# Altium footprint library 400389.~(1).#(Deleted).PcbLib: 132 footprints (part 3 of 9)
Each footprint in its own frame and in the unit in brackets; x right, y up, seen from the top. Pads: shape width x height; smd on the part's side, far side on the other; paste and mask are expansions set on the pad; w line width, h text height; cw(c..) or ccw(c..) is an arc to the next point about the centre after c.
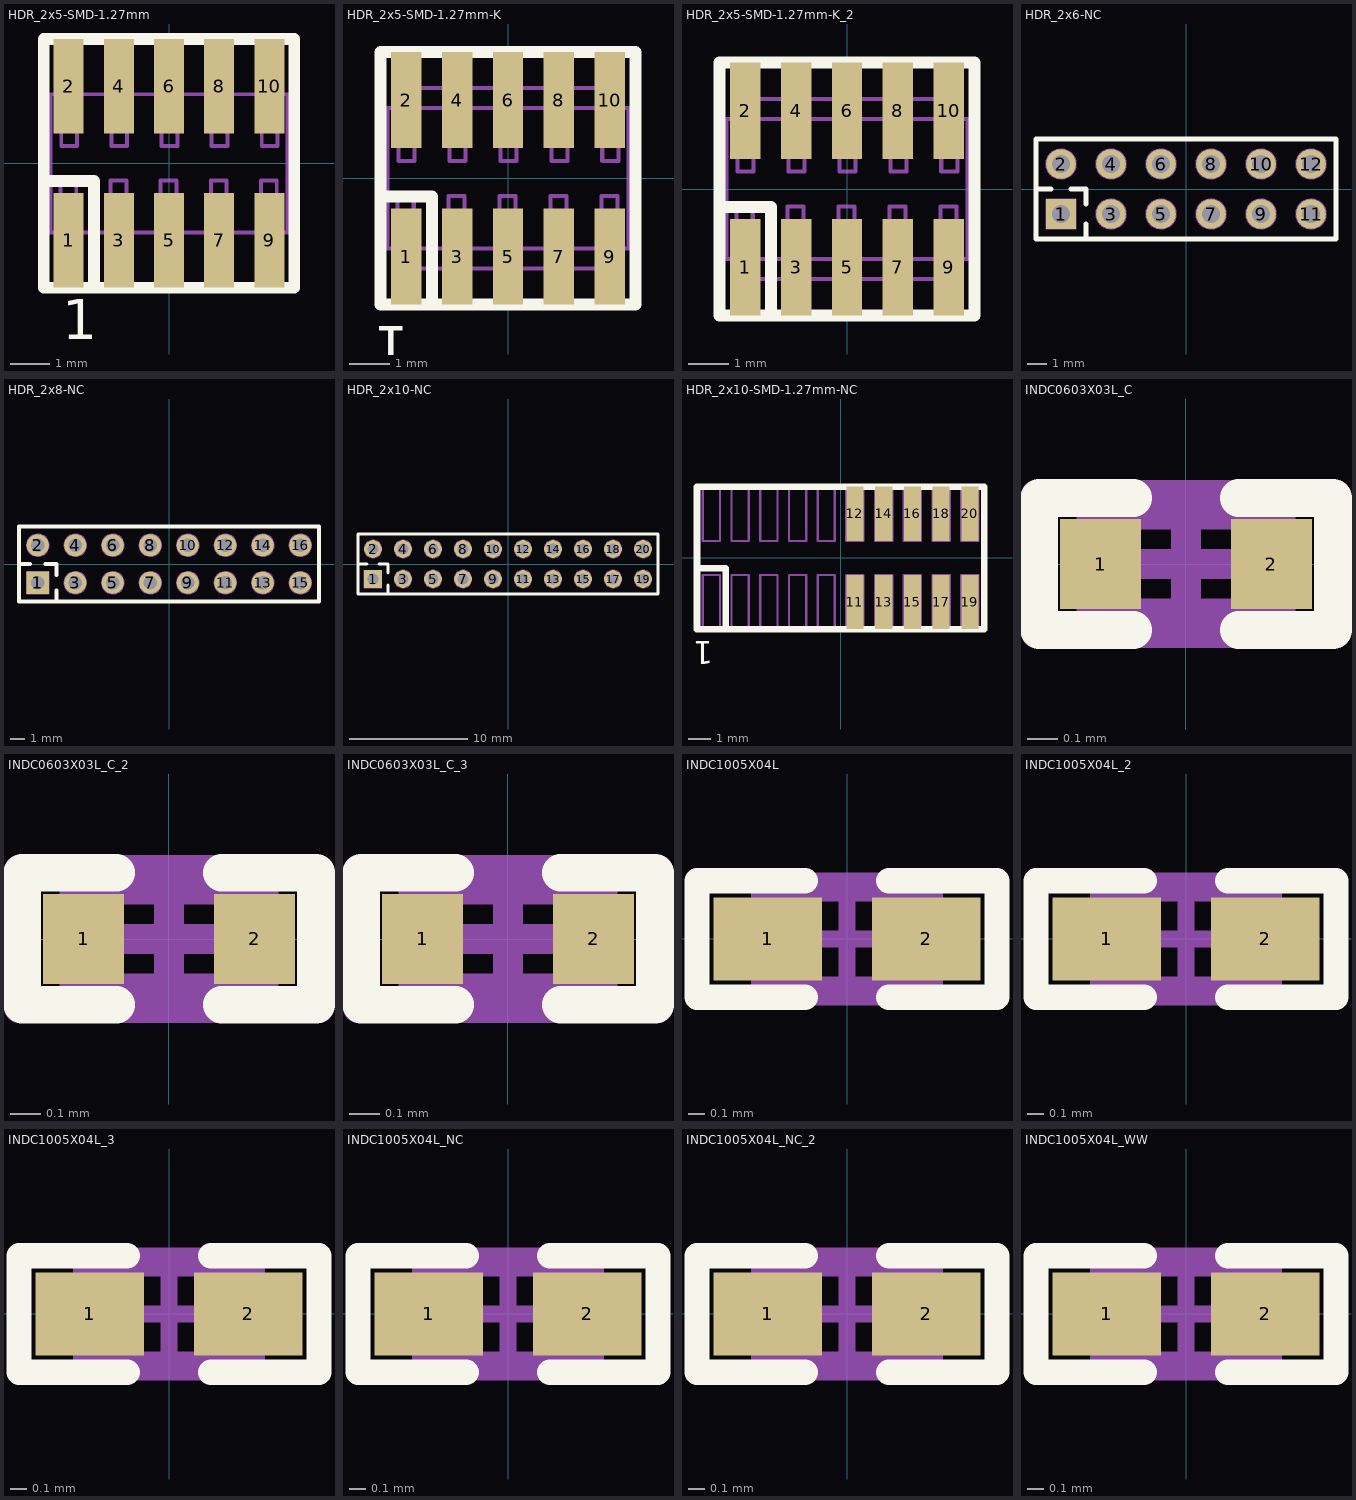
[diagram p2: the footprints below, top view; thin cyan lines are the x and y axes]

## HDR_2x5-SMD-1.27mm [mm]
pads (10):
  rect 0.76x2.4 smd: 1(-2.54,-1.95) 2(-2.54,1.95) 3(-1.27,-1.95) 4(-1.27,1.95) 5(0,-1.95) 6(0,1.95) 7(1.27,-1.95) 8(1.27,1.95) 9(2.54,-1.95) 10(2.54,1.95)
Top Overlay:
  lines w0.3: -3.175,-0.45 -1.9,-0.45 -1.9,-3.15 ; -3.175,-3.15 -3.175,3.15 3.175,3.15 3.175,-3.15 -3.175,-3.15
  text "1" at -2.7,-4.45 h1.02
Mechanical 7:
  lines w0.1: -2.74,-1.75 -2.74,-2.459 ccw(c-2.54,-2.459) -2.34,-2.459 -2.34,-1.75 ; -2.74,1.75 -2.74,2.459 cw(c-2.54,2.459) -2.34,2.459 -2.34,1.75 ; -1.47,-1.75 -1.47,-2.459 ccw(c-1.27,-2.459) -1.07,-2.459 -1.07,-1.75 ; -1.47,1.75 -1.47,2.459 cw(c-1.27,2.459) -1.07,2.459 -1.07,1.75 ; -0.2,-1.75 -0.2,-2.459 ccw(c0,-2.459) 0.2,-2.459 0.2,-1.75 ; -0.2,1.75 -0.2,2.459 cw(c0,2.459) 0.2,2.459 0.2,1.75 ; 1.07,-1.75 1.07,-2.459 ccw(c1.27,-2.459) 1.47,-2.459 1.47,-1.75 ; 1.07,1.75 1.07,2.459 cw(c1.27,2.459) 1.47,2.459 1.47,1.75 ; 2.34,-1.75 2.34,-2.459 ccw(c2.54,-2.459) 2.74,-2.459 2.74,-1.75 ; 2.34,1.75 2.34,2.459 cw(c2.54,2.459) 2.74,2.459 2.74,1.75 ; -3,-1.75 3,-1.75 3,1.75 -3,1.75 -3,-1.75 ; -2.75,-0.835 -2.35,-0.835 -2.35,-0.435 -2.75,-0.435 -2.75,-0.835 ; -2.73,0.435 -2.33,0.435 -2.33,0.835 -2.73,0.835 -2.73,0.435 ; -1.48,-0.835 -1.08,-0.835 -1.08,-0.435 -1.48,-0.435 -1.48,-0.835 ; -1.46,0.435 -1.06,0.435 -1.06,0.835 -1.46,0.835 -1.46,0.435 ; -0.21,-0.835 0.19,-0.835 0.19,-0.435 -0.21,-0.435 -0.21,-0.835 ; -0.19,0.435 0.21,0.435 0.21,0.835 -0.19,0.835 -0.19,0.435 ; 1.06,-0.835 1.46,-0.835 1.46,-0.435 1.06,-0.435 1.06,-0.835 ; 1.08,0.435 1.48,0.435 1.48,0.835 1.08,0.835 1.08,0.435 ; 2.33,-0.835 2.73,-0.835 2.73,-0.435 2.33,-0.435 2.33,-0.835 ; 2.35,0.435 2.75,0.435 2.75,0.835 2.35,0.835 2.35,0.435
  text ".Designator" at -0.8,-0.2 h0.38
3D body "Samtec-FTS-105-01-F-DV.step": height 4.33, standoff 0.01, extent -3.165,-2.921 3.185,2.921

## HDR_2x5-SMD-1.27mm-K [mm]
pads (10):
  rect 0.76x2.4 smd: 1(-2.54,-1.95) 2(-2.54,1.95) 3(-1.27,-1.95) 4(-1.27,1.95) 5(0,-1.95) 6(0,1.95) 7(1.27,-1.95) 8(1.27,1.95) 9(2.54,-1.95) 10(2.54,1.95)
Top Overlay:
  lines w0.3: -3.175,-0.45 -1.9,-0.45 -1.9,-3.15 ; -3.175,-3.15 -3.175,3.15 3.175,3.15 3.175,-3.15 -3.175,-3.15
  text "1" at -2.448,-3.683 h1.02
Mechanical 7:
  lines w0.1: -2.74,-1.75 -2.74,-2.459 ccw(c-2.54,-2.459) -2.34,-2.459 -2.34,-2.25 ; -2.74,1.75 -2.74,2.459 cw(c-2.54,2.459) -2.34,2.459 -2.34,2.25 ; -2.5,-1.75 -2.5,-2.25 -1.25,-2.25 ; -2.5,1.75 -2.5,2.25 2.5,2.25 2.5,1.75 ; -1.47,-2.25 -1.47,-2.459 ccw(c-1.27,-2.459) -1.07,-2.459 -1.07,-2.25 ; -1.47,2.25 -1.47,2.459 cw(c-1.27,2.459) -1.07,2.459 -1.07,2.25 ; -1.25,-1.75 -1.25,-2.25 ; -0.2,-2.25 -0.2,-2.459 ccw(c0,-2.459) 0.2,-2.459 0.2,-2.25 ; -0.2,2.25 -0.2,2.459 cw(c0,2.459) 0.2,2.459 0.2,2.25 ; 1.07,-2.25 1.07,-2.459 ccw(c1.27,-2.459) 1.47,-2.459 1.47,-2.25 ; 1.07,2.25 1.07,2.459 cw(c1.27,2.459) 1.47,2.459 1.47,2.25 ; 1.25,-1.75 1.25,-2.25 ; 2.34,-2.25 2.34,-2.459 ccw(c2.54,-2.459) 2.74,-2.459 2.74,-1.75 ; 2.34,2.25 2.34,2.459 cw(c2.54,2.459) 2.74,2.459 2.74,1.75 ; 2.5,-1.75 2.5,-2.25 1.25,-2.25 ; -1.25,-2.25 1.25,-2.25 ; -3,-1.75 -3,1.75 3,1.75 3,-1.75 -3,-1.75 ; -2.75,-0.835 -2.75,-0.435 -2.35,-0.435 -2.35,-0.835 -2.75,-0.835 ; -2.73,0.435 -2.73,0.835 -2.33,0.835 -2.33,0.435 -2.73,0.435 ; -1.48,-0.835 -1.48,-0.435 -1.08,-0.435 -1.08,-0.835 -1.48,-0.835 ; -1.46,0.435 -1.46,0.835 -1.06,0.835 -1.06,0.435 -1.46,0.435 ; -0.21,-0.835 -0.21,-0.435 0.19,-0.435 0.19,-0.835 -0.21,-0.835 ; -0.19,0.435 -0.19,0.835 0.21,0.835 0.21,0.435 -0.19,0.435 ; 1.06,-0.835 1.06,-0.435 1.46,-0.435 1.46,-0.835 1.06,-0.835 ; 1.08,0.435 1.08,0.835 1.48,0.835 1.48,0.435 1.08,0.435 ; 2.33,-0.835 2.33,-0.435 2.73,-0.435 2.73,-0.835 2.33,-0.835 ; 2.35,0.435 2.35,0.835 2.75,0.835 2.75,0.435 2.35,0.435
  text ".Designator" at -0.8,-0.2 h0.38
3D body "Samtec-FTSH-105-01-F-DV-K.step": height 6.11, standoff -0.01, extent -3.137,-2.921 3.137,2.921

## HDR_2x5-SMD-1.27mm-K_2 [mm]
pads (10):
  rect 0.76x2.4 smd: 1(-2.54,-1.95) 2(-2.54,1.95) 3(-1.27,-1.95) 4(-1.27,1.95) 5(0,-1.95) 6(0,1.95) 7(1.27,-1.95) 8(1.27,1.95) 9(2.54,-1.95) 10(2.54,1.95)
Top Overlay:
  lines w0.3: -3.175,-0.45 -1.9,-0.45 -1.9,-3.15 ; -3.175,-3.15 -3.175,3.15 3.175,3.15 3.175,-3.15 -3.175,-3.15
Mechanical 7:
  lines w0.1: -2.74,-1.75 -2.74,-2.459 ccw(c-2.54,-2.459) -2.34,-2.459 -2.34,-2.25 ; -2.74,1.75 -2.74,2.459 cw(c-2.54,2.459) -2.34,2.459 -2.34,2.25 ; -2.5,-1.75 -2.5,-2.25 -1.25,-2.25 ; -2.5,1.75 -2.5,2.25 2.5,2.25 2.5,1.75 ; -1.47,-2.25 -1.47,-2.459 ccw(c-1.27,-2.459) -1.07,-2.459 -1.07,-2.25 ; -1.47,2.25 -1.47,2.459 cw(c-1.27,2.459) -1.07,2.459 -1.07,2.25 ; -1.25,-1.75 -1.25,-2.25 ; -0.2,-2.25 -0.2,-2.459 ccw(c0,-2.459) 0.2,-2.459 0.2,-2.25 ; -0.2,2.25 -0.2,2.459 cw(c0,2.459) 0.2,2.459 0.2,2.25 ; 1.07,-2.25 1.07,-2.459 ccw(c1.27,-2.459) 1.47,-2.459 1.47,-2.25 ; 1.07,2.25 1.07,2.459 cw(c1.27,2.459) 1.47,2.459 1.47,2.25 ; 1.25,-1.75 1.25,-2.25 ; 2.34,-2.25 2.34,-2.459 ccw(c2.54,-2.459) 2.74,-2.459 2.74,-1.75 ; 2.34,2.25 2.34,2.459 cw(c2.54,2.459) 2.74,2.459 2.74,1.75 ; 2.5,-1.75 2.5,-2.25 1.25,-2.25 ; -1.25,-2.25 1.25,-2.25 ; -3,-1.75 -3,1.75 3,1.75 3,-1.75 -3,-1.75 ; -2.75,-0.835 -2.75,-0.435 -2.35,-0.435 -2.35,-0.835 -2.75,-0.835 ; -2.73,0.435 -2.73,0.835 -2.33,0.835 -2.33,0.435 -2.73,0.435 ; -1.48,-0.835 -1.48,-0.435 -1.08,-0.435 -1.08,-0.835 -1.48,-0.835 ; -1.46,0.435 -1.46,0.835 -1.06,0.835 -1.06,0.435 -1.46,0.435 ; -0.21,-0.835 -0.21,-0.435 0.19,-0.435 0.19,-0.835 -0.21,-0.835 ; -0.19,0.435 -0.19,0.835 0.21,0.835 0.21,0.435 -0.19,0.435 ; 1.06,-0.835 1.06,-0.435 1.46,-0.435 1.46,-0.835 1.06,-0.835 ; 1.08,0.435 1.08,0.835 1.48,0.835 1.48,0.435 1.08,0.435 ; 2.33,-0.835 2.33,-0.435 2.73,-0.435 2.73,-0.835 2.33,-0.835 ; 2.35,0.435 2.35,0.835 2.75,0.835 2.75,0.435 2.35,0.435
  text ".Designator" at -0.8,-0.2 h0.38
3D body "Samtec-FTSH-105-01-F-DV-K.step": height 6.11, standoff -0.01, extent -3.137,-2.921 3.137,2.921

## HDR_2x6-NC [mm]
pads (12):
  rect 1.5x1.5 hole 0.9: 1(-6.35,-1.27)
  round 1.5 hole 0.9: 2(-6.35,1.27) 3(-3.81,-1.27) 4(-3.81,1.27) 5(-1.27,-1.27) 6(-1.27,1.27) 7(1.27,-1.27) 8(1.27,1.27) 9(3.81,-1.27) 10(3.81,1.27) 11(6.35,-1.27) 12(6.35,1.27)
Top Overlay:
  lines w0.254: -7.62,0 -6.858,0 ; -5.842,0 -5.08,0 -5.08,-0.762 ; -5.08,-2.54 -5.08,-1.778 ; -7.62,-2.54 -7.62,2.54 7.62,2.54 7.62,-2.54 -7.62,-2.54
Mechanical 7:
  circle w0.1: c-6.35,-1.27 r0.45
  circle w0.1: c-3.81,-1.27 r0.45
  circle w0.1: c-3.81,-1.27 r0.75
  circle w0.1: c-6.35,1.27 r0.75
  circle w0.1: c-6.35,1.27 r0.45
  circle w0.1: c-3.81,1.27 r0.75
  circle w0.1: c-3.81,1.27 r0.45
  circle w0.1: c-1.27,1.27 r0.45
  circle w0.1: c-1.27,1.27 r0.75
  circle w0.1: c-1.27,-1.27 r0.75
  circle w0.1: c-1.27,-1.27 r0.45
  circle w0.1: c1.27,1.27 r0.45
  circle w0.1: c1.27,1.27 r0.75
  circle w0.1: c1.27,-1.27 r0.75
  circle w0.1: c1.27,-1.27 r0.45
  circle w0.1: c3.81,1.27 r0.45
  circle w0.1: c3.81,1.27 r0.75
  circle w0.1: c3.81,-1.27 r0.75
  circle w0.1: c3.81,-1.27 r0.45
  circle w0.1: c6.35,1.27 r0.45
  circle w0.1: c6.35,1.27 r0.75
  circle w0.1: c6.35,-1.27 r0.75
  circle w0.1: c6.35,-1.27 r0.45
  lines w0.1: -7.62,0 -6.858,0 ; -5.842,0 -5.08,0 -5.08,-0.762 ; -5.08,-2.54 -5.08,-1.778 ; -7.62,-2.54 7.62,-2.54 7.62,2.54 -7.62,2.54 -7.62,-2.54 ; -7.1,-2.02 -7.1,-0.52 -5.6,-0.52 -5.6,-2.02 -7.1,-2.02
  text ".Designator" at -0.525,-0.1 h0.31
Mechanical 8:
  circle w0.1: c6.35,-1.27 r0.45
  circle w0.1: c6.35,-1.27 r0.75
  circle w0.1: c6.35,1.27 r0.75
  circle w0.1: c6.35,1.27 r0.45
  circle w0.1: c3.81,-1.27 r0.45
  circle w0.1: c3.81,-1.27 r0.75
  circle w0.1: c3.81,1.27 r0.75
  circle w0.1: c3.81,1.27 r0.45
  circle w0.1: c1.27,-1.27 r0.45
  circle w0.1: c1.27,-1.27 r0.75
  circle w0.1: c1.27,1.27 r0.75
  circle w0.1: c1.27,1.27 r0.45
  circle w0.1: c-1.27,-1.27 r0.45
  circle w0.1: c-1.27,-1.27 r0.75
  circle w0.1: c-1.27,1.27 r0.75
  circle w0.1: c-1.27,1.27 r0.45
  circle w0.1: c-3.81,1.27 r0.45
  circle w0.1: c-3.81,1.27 r0.75
  circle w0.1: c-6.35,1.27 r0.45
  circle w0.1: c-6.35,1.27 r0.75
  circle w0.1: c-3.81,-1.27 r0.75
  circle w0.1: c-3.81,-1.27 r0.45
  circle w0.1: c-6.35,-1.27 r0.45
  lines w0.1: -7.1,-2.02 -5.6,-2.02 -5.6,-0.52 -7.1,-0.52 -7.1,-2.02

## HDR_2x8-NC [mm]
pads (16):
  rect 1.5x1.5 hole 0.9: 1(-8.89,-1.27)
  round 1.5 hole 0.9: 2(-8.89,1.27) 3(-6.35,-1.27) 4(-6.35,1.27) 5(-3.81,-1.27) 6(-3.81,1.27) 7(-1.27,-1.27) 8(-1.27,1.27) 9(1.27,-1.27) 10(1.27,1.27) 11(3.81,-1.27) 12(3.81,1.27) 13(6.35,-1.27) 14(6.35,1.27) 15(8.89,-1.27) 16(8.89,1.27)
Top Overlay:
  lines w0.254: -10.16,0 -9.398,0 ; -8.382,0 -7.62,0 -7.62,-0.762 ; -7.62,-2.54 -7.62,-1.778 ; -10.16,-2.54 10.16,-2.54 10.16,2.54 -10.16,2.54 -10.16,-2.54
Mechanical 7:
  circle w0.1: c8.89,-1.27 r0.45
  circle w0.1: c8.89,-1.27 r0.75
  circle w0.1: c8.89,1.27 r0.75
  circle w0.1: c8.89,1.27 r0.45
  circle w0.1: c6.35,-1.27 r0.45
  circle w0.1: c6.35,-1.27 r0.75
  circle w0.1: c6.35,1.27 r0.75
  circle w0.1: c6.35,1.27 r0.45
  circle w0.1: c3.81,-1.27 r0.45
  circle w0.1: c3.81,-1.27 r0.75
  circle w0.1: c3.81,1.27 r0.75
  circle w0.1: c3.81,1.27 r0.45
  circle w0.1: c1.27,-1.27 r0.45
  circle w0.1: c1.27,-1.27 r0.75
  circle w0.1: c1.27,1.27 r0.75
  circle w0.1: c1.27,1.27 r0.45
  circle w0.1: c-1.27,-1.27 r0.45
  circle w0.1: c-1.27,-1.27 r0.75
  circle w0.1: c-1.27,1.27 r0.75
  circle w0.1: c-1.27,1.27 r0.45
  circle w0.1: c-3.81,-1.27 r0.45
  circle w0.1: c-3.81,-1.27 r0.75
  circle w0.1: c-3.81,1.27 r0.75
  circle w0.1: c-3.81,1.27 r0.45
  circle w0.1: c-6.35,1.27 r0.45
  circle w0.1: c-6.35,1.27 r0.75
  circle w0.1: c-8.89,1.27 r0.45
  circle w0.1: c-8.89,1.27 r0.75
  circle w0.1: c-6.35,-1.27 r0.75
  circle w0.1: c-6.35,-1.27 r0.45
  circle w0.1: c-8.89,-1.27 r0.45
  lines w0.1: -10.16,0 -9.398,0 ; -8.382,0 -7.62,0 -7.62,-0.762 ; -7.62,-2.54 -7.62,-1.778 ; -10.16,-2.54 -10.16,2.54 10.16,2.54 10.16,-2.54 -10.16,-2.54 ; -9.64,-2.02 -8.14,-2.02 -8.14,-0.52 -9.64,-0.52 -9.64,-2.02
  text ".Designator" at -0.525,-0.1 h0.31
Mechanical 8:
  circle w0.1: c-8.89,-1.27 r0.45
  circle w0.1: c-6.35,-1.27 r0.45
  circle w0.1: c-6.35,-1.27 r0.75
  circle w0.1: c-8.89,1.27 r0.75
  circle w0.1: c-8.89,1.27 r0.45
  circle w0.1: c-6.35,1.27 r0.75
  circle w0.1: c-6.35,1.27 r0.45
  circle w0.1: c-3.81,1.27 r0.45
  circle w0.1: c-3.81,1.27 r0.75
  circle w0.1: c-3.81,-1.27 r0.75
  circle w0.1: c-3.81,-1.27 r0.45
  circle w0.1: c-1.27,1.27 r0.45
  circle w0.1: c-1.27,1.27 r0.75
  circle w0.1: c-1.27,-1.27 r0.75
  circle w0.1: c-1.27,-1.27 r0.45
  circle w0.1: c1.27,1.27 r0.45
  circle w0.1: c1.27,1.27 r0.75
  circle w0.1: c1.27,-1.27 r0.75
  circle w0.1: c1.27,-1.27 r0.45
  circle w0.1: c3.81,1.27 r0.45
  circle w0.1: c3.81,1.27 r0.75
  circle w0.1: c3.81,-1.27 r0.75
  circle w0.1: c3.81,-1.27 r0.45
  circle w0.1: c6.35,1.27 r0.45
  circle w0.1: c6.35,1.27 r0.75
  circle w0.1: c6.35,-1.27 r0.75
  circle w0.1: c6.35,-1.27 r0.45
  circle w0.1: c8.89,1.27 r0.45
  circle w0.1: c8.89,1.27 r0.75
  circle w0.1: c8.89,-1.27 r0.75
  circle w0.1: c8.89,-1.27 r0.45
  lines w0.1: -9.64,-2.02 -9.64,-0.52 -8.14,-0.52 -8.14,-2.02 -9.64,-2.02

## HDR_2x10-NC [mm]
pads (20):
  rect 1.5x1.5 hole 0.9: 1(-11.43,-1.27)
  round 1.5 hole 0.9: 2(-11.43,1.27) 3(-8.89,-1.27) 4(-8.89,1.27) 5(-6.35,-1.27) 6(-6.35,1.27) 7(-3.81,-1.27) 8(-3.81,1.27) 9(-1.27,-1.27) 10(-1.27,1.27) 11(1.27,-1.27) 12(1.27,1.27) 13(3.81,-1.27) 14(3.81,1.27) 15(6.35,-1.27) 16(6.35,1.27) 17(8.89,-1.27) 18(8.89,1.27) 19(11.43,-1.27) 20(11.43,1.27)
Top Overlay:
  lines w0.254: -12.7,0 -11.938,0 ; -10.922,0 -10.16,0 -10.16,-0.762 ; -10.16,-2.54 -10.16,-1.778 ; -12.7,-2.54 12.7,-2.54 12.7,2.54 -12.7,2.54 -12.7,-2.54
Mechanical 7:
  circle w0.1: c11.43,-1.27 r0.45
  circle w0.1: c11.43,-1.27 r0.75
  circle w0.1: c11.43,1.27 r0.75
  circle w0.1: c11.43,1.27 r0.45
  circle w0.1: c8.89,-1.27 r0.45
  circle w0.1: c8.89,-1.27 r0.75
  circle w0.1: c8.89,1.27 r0.75
  circle w0.1: c8.89,1.27 r0.45
  circle w0.1: c6.35,-1.27 r0.45
  circle w0.1: c6.35,-1.27 r0.75
  circle w0.1: c6.35,1.27 r0.75
  circle w0.1: c6.35,1.27 r0.45
  circle w0.1: c3.81,-1.27 r0.45
  circle w0.1: c3.81,-1.27 r0.75
  circle w0.1: c3.81,1.27 r0.75
  circle w0.1: c3.81,1.27 r0.45
  circle w0.1: c1.27,-1.27 r0.45
  circle w0.1: c1.27,-1.27 r0.75
  circle w0.1: c1.27,1.27 r0.75
  circle w0.1: c1.27,1.27 r0.45
  circle w0.1: c-1.27,-1.27 r0.45
  circle w0.1: c-1.27,-1.27 r0.75
  circle w0.1: c-1.27,1.27 r0.75
  circle w0.1: c-1.27,1.27 r0.45
  circle w0.1: c-3.81,-1.27 r0.45
  circle w0.1: c-3.81,-1.27 r0.75
  circle w0.1: c-3.81,1.27 r0.75
  circle w0.1: c-3.81,1.27 r0.45
  circle w0.1: c-6.35,-1.27 r0.45
  circle w0.1: c-6.35,-1.27 r0.75
  circle w0.1: c-6.35,1.27 r0.75
  circle w0.1: c-6.35,1.27 r0.45
  circle w0.1: c-8.89,1.27 r0.45
  circle w0.1: c-8.89,1.27 r0.75
  circle w0.1: c-11.43,1.27 r0.45
  circle w0.1: c-11.43,1.27 r0.75
  circle w0.1: c-8.89,-1.27 r0.75
  circle w0.1: c-8.89,-1.27 r0.45
  circle w0.1: c-11.43,-1.27 r0.45
  lines w0.1: -12.7,0 -11.938,0 ; -10.922,0 -10.16,0 -10.16,-0.762 ; -10.16,-2.54 -10.16,-1.778 ; -12.7,-2.54 -12.7,2.54 12.7,2.54 12.7,-2.54 -12.7,-2.54 ; -12.18,-2.02 -10.68,-2.02 -10.68,-0.52 -12.18,-0.52 -12.18,-2.02
  text ".Designator" at -0.525,-0.1 h0.31
Mechanical 8:
  circle w0.1: c-11.43,-1.27 r0.45
  circle w0.1: c-8.89,-1.27 r0.45
  circle w0.1: c-8.89,-1.27 r0.75
  circle w0.1: c-11.43,1.27 r0.75
  circle w0.1: c-11.43,1.27 r0.45
  circle w0.1: c-8.89,1.27 r0.75
  circle w0.1: c-8.89,1.27 r0.45
  circle w0.1: c-6.35,1.27 r0.45
  circle w0.1: c-6.35,1.27 r0.75
  circle w0.1: c-6.35,-1.27 r0.75
  circle w0.1: c-6.35,-1.27 r0.45
  circle w0.1: c-3.81,1.27 r0.45
  circle w0.1: c-3.81,1.27 r0.75
  circle w0.1: c-3.81,-1.27 r0.75
  circle w0.1: c-3.81,-1.27 r0.45
  circle w0.1: c-1.27,1.27 r0.45
  circle w0.1: c-1.27,1.27 r0.75
  circle w0.1: c-1.27,-1.27 r0.75
  circle w0.1: c-1.27,-1.27 r0.45
  circle w0.1: c1.27,1.27 r0.45
  circle w0.1: c1.27,1.27 r0.75
  circle w0.1: c1.27,-1.27 r0.75
  circle w0.1: c1.27,-1.27 r0.45
  circle w0.1: c3.81,1.27 r0.45
  circle w0.1: c3.81,1.27 r0.75
  circle w0.1: c3.81,-1.27 r0.75
  circle w0.1: c3.81,-1.27 r0.45
  circle w0.1: c6.35,1.27 r0.45
  circle w0.1: c6.35,1.27 r0.75
  circle w0.1: c6.35,-1.27 r0.75
  circle w0.1: c6.35,-1.27 r0.45
  circle w0.1: c8.89,1.27 r0.45
  circle w0.1: c8.89,1.27 r0.75
  circle w0.1: c8.89,-1.27 r0.75
  circle w0.1: c8.89,-1.27 r0.45
  circle w0.1: c11.43,1.27 r0.45
  circle w0.1: c11.43,1.27 r0.75
  circle w0.1: c11.43,-1.27 r0.75
  circle w0.1: c11.43,-1.27 r0.45
  lines w0.1: -12.18,-2.02 -12.18,-0.52 -10.68,-0.52 -10.68,-2.02 -12.18,-2.02

## HDR_2x10-SMD-1.27mm-NC [mm]
pads (10):
  rect 0.76x2.4 smd paste-1.27: 11(0.635,-1.95) 12(0.635,1.95) 13(1.905,-1.95) 14(1.905,1.95) 15(3.175,-1.95) 16(3.175,1.95) 17(4.445,-1.95) 18(4.445,1.95) 19(5.715,-1.95) 20(5.715,1.95)
Top Overlay:
  lines w0.3: -6.35,-0.45 -5.075,-0.45 -5.075,-3.15 ; -6.35,-3.15 6.35,-3.15 6.35,3.15 -6.35,3.15 -6.35,-3.15
  text "1" at -5.622,-3.683 h1.02
Mechanical 7:
  lines w0.1: -6.35,-3.15 -6.35,3.15 6.35,3.15 6.35,-3.15 -6.35,-3.15 ; -6.095,-3.15 -6.095,-0.75 -5.335,-0.75 -5.335,-3.15 -6.095,-3.15 ; -6.095,0.75 -6.095,3.15 -5.335,3.15 -5.335,0.75 -6.095,0.75 ; -4.825,-3.15 -4.825,-0.75 -4.065,-0.75 -4.065,-3.15 -4.825,-3.15 ; -4.825,0.75 -4.825,3.15 -4.065,3.15 -4.065,0.75 -4.825,0.75 ; -3.555,-3.15 -3.555,-0.75 -2.795,-0.75 -2.795,-3.15 -3.555,-3.15 ; -3.555,0.75 -2.795,0.75 -2.795,3.15 -3.555,3.15 -3.555,0.75 ; -2.285,-3.15 -2.285,-0.75 -1.525,-0.75 -1.525,-3.15 -2.285,-3.15 ; -2.285,0.75 -2.285,3.15 -1.525,3.15 -1.525,0.75 -2.285,0.75 ; -1.015,-3.15 -1.015,-0.75 -0.255,-0.75 -0.255,-3.15 -1.015,-3.15 ; -1.015,0.75 -1.015,3.15 -0.255,3.15 -0.255,0.75 -1.015,0.75 ; 0.255,-3.15 0.255,-0.75 1.015,-0.75 1.015,-3.15 0.255,-3.15 ; 0.255,0.75 0.255,3.15 1.015,3.15 1.015,0.75 0.255,0.75 ; 1.525,-3.15 1.525,-0.75 2.285,-0.75 2.285,-3.15 1.525,-3.15 ; 1.525,0.75 1.525,3.15 2.285,3.15 2.285,0.75 1.525,0.75 ; 2.795,-3.15 2.795,-0.75 3.555,-0.75 3.555,-3.15 2.795,-3.15 ; 2.795,0.75 2.795,3.15 3.555,3.15 3.555,0.75 2.795,0.75 ; 4.065,-3.15 4.065,-0.75 4.825,-0.75 4.825,-3.15 4.065,-3.15 ; 4.065,0.75 4.065,3.15 4.825,3.15 4.825,0.75 4.065,0.75 ; 5.335,-3.15 5.335,-0.75 6.095,-0.75 6.095,-3.15 5.335,-3.15 ; 5.335,0.75 5.335,3.15 6.095,3.15 6.095,0.75 5.335,0.75
  text ".Designator" at -0.8,-0.2 h0.38

## INDC0603X03L_C [mm]
pads (2):
  rect 0.27x0.3 smd: 1(-0.285,0) 2(0.285,0)
Top Overlay:
  lines w0.125: -0.175,-0.22 -0.49,-0.22 -0.49,0.22 -0.175,0.22 ; 0.175,-0.22 0.49,-0.22 0.49,0.22 0.175,0.22
Mechanical 7:
  lines w0.1: -0.315,-0.165 0.315,-0.165 0.315,0.165 -0.315,0.165 -0.315,-0.165
  text ".Designator" at -0.306,0.268 h0.3
Mechanical 15:
  lines w0.1: -0.165,0 0.165,0 ; 0,-0.165 0,0.165 ; -0.5,-0.23 0.5,-0.23 0.5,0.23 -0.5,0.23 -0.5,-0.23
3D body "User Library-smt_inductor-0201.step": height 0.26, standoff -0.01, extent -0.31,-0.16 0.31,0.16

## INDC0603X03L_C_2 [mm]
pads (2):
  rect 0.27x0.3 smd: 1(-0.285,0) 2(0.285,0)
Top Overlay:
  lines w0.125: -0.175,-0.22 -0.49,-0.22 -0.49,0.22 -0.175,0.22 ; 0.175,-0.22 0.49,-0.22 0.49,0.22 0.175,0.22
Mechanical 7:
  lines w0.1: -0.315,-0.165 0.315,-0.165 0.315,0.165 -0.315,0.165 -0.315,-0.165
  text ".Designator" at -0.306,0.268 h0.3
Mechanical 15:
  lines w0.1: -0.165,0 0.165,0 ; 0,-0.165 0,0.165 ; -0.5,-0.23 0.5,-0.23 0.5,0.23 -0.5,0.23 -0.5,-0.23
3D body "User Library-smt_inductor-0201.step": height 0.26, standoff -0.01, extent -0.31,-0.16 0.31,0.16

## INDC0603X03L_C_3 [mm]
pads (2):
  rect 0.27x0.3 smd: 1(-0.285,0) 2(0.285,0)
Top Overlay:
  lines w0.125: -0.175,-0.22 -0.49,-0.22 -0.49,0.22 -0.175,0.22 ; 0.175,-0.22 0.49,-0.22 0.49,0.22 0.175,0.22
Mechanical 7:
  lines w0.1: -0.315,-0.165 -0.315,0.165 0.315,0.165 0.315,-0.165 -0.315,-0.165
  text ".Designator" at -0.306,0.268 h0.3
Mechanical 15:
  lines w0.1: -0.165,0 0.165,0 ; 0,-0.165 0,0.165 ; -0.5,-0.23 -0.5,0.23 0.5,0.23 0.5,-0.23 -0.5,-0.23
3D body "User Library-smt_inductor-0201.step": height 0.26, standoff -0.01, extent -0.31,-0.16 0.31,0.16

## INDC1005X04L [mm]
pads (2):
  rect 0.65x0.5 smd: 1(-0.475,0) 2(0.475,0)
Top Overlay:
  lines w0.152: -0.25,-0.35 -0.9,-0.35 -0.9,0.35 -0.25,0.35 ; 0.25,-0.35 0.9,-0.35 0.9,0.35 0.25,0.35
Mechanical 7:
  lines w0.1: -0.525,-0.275 0.525,-0.275 0.525,0.275 -0.525,0.275 -0.525,-0.275
  text ".Designator" at -0.432,-0.152 h0.3
Mechanical 15:
  lines w0.1: -0.275,0 0.275,0 ; 0,-0.275 0,0.275 ; -0.9,-0.35 0.9,-0.35 0.9,0.35 -0.9,0.35 -0.9,-0.35
3D body "User Library-Chip Inductor 0402.step": height 0.5, standoff 0, extent -0.5,-0.3 0.5,0.3

## INDC1005X04L_2 [mm]
pads (2):
  rect 0.65x0.5 smd: 1(-0.475,0) 2(0.475,0)
Top Overlay:
  lines w0.152: -0.25,-0.35 -0.9,-0.35 -0.9,0.35 -0.25,0.35 ; 0.25,-0.35 0.9,-0.35 0.9,0.35 0.25,0.35
Mechanical 7:
  lines w0.1: -0.525,-0.275 -0.525,0.275 0.525,0.275 0.525,-0.275 -0.525,-0.275
  text ".Designator" at -0.432,-0.152 h0.3
Mechanical 15:
  lines w0.1: -0.275,0 0.275,0 ; 0,-0.275 0,0.275 ; -0.9,-0.35 -0.9,0.35 0.9,0.35 0.9,-0.35 -0.9,-0.35
3D body "User Library-Chip Inductor 0402.step": height 0.5, standoff 0, extent -0.5,-0.3 0.5,0.3

## INDC1005X04L_3 [mm]
pads (2):
  rect 0.65x0.5 smd: 1(-0.475,0) 2(0.475,0)
Top Overlay:
  lines w0.152: -0.25,-0.35 -0.9,-0.35 -0.9,0.35 -0.25,0.35 ; 0.25,-0.35 0.9,-0.35 0.9,0.35 0.25,0.35
Mechanical 7:
  lines w0.1: -0.525,-0.275 -0.525,0.275 0.525,0.275 0.525,-0.275 -0.525,-0.275
  text ".Designator" at -0.432,-0.152 h0.3
Mechanical 15:
  lines w0.1: -0.275,0 0.275,0 ; 0,-0.275 0,0.275 ; -0.9,-0.35 -0.9,0.35 0.9,0.35 0.9,-0.35 -0.9,-0.35
3D body "User Library-Chip Inductor 0402.step": height 0.5, standoff 0, extent -0.5,-0.3 0.5,0.3

## INDC1005X04L_NC [mm]
pads (2):
  rect 0.65x0.5 smd: 1(-0.475,0) 2(0.475,0)
Top Overlay:
  lines w0.152: -0.25,-0.35 -0.9,-0.35 -0.9,0.35 -0.25,0.35 ; 0.25,-0.35 0.9,-0.35 0.9,0.35 0.25,0.35
Mechanical 7:
  lines w0.1: -0.525,-0.275 0.525,-0.275 0.525,0.275 -0.525,0.275 -0.525,-0.275
  text ".Designator" at -0.432,-0.152 h0.3
Mechanical 15:
  lines w0.1: -0.275,0 0.275,0 ; 0,-0.275 0,0.275 ; -0.9,-0.35 0.9,-0.35 0.9,0.35 -0.9,0.35 -0.9,-0.35

## INDC1005X04L_NC_2 [mm]
pads (2):
  rect 0.65x0.5 smd: 1(-0.475,0) 2(0.475,0)
Top Overlay:
  lines w0.152: -0.25,-0.35 -0.9,-0.35 -0.9,0.35 -0.25,0.35 ; 0.25,-0.35 0.9,-0.35 0.9,0.35 0.25,0.35
Mechanical 7:
  lines w0.1: -0.525,-0.275 0.525,-0.275 0.525,0.275 -0.525,0.275 -0.525,-0.275
  text ".Designator" at -0.432,-0.152 h0.3
Mechanical 15:
  lines w0.1: -0.275,0 0.275,0 ; 0,-0.275 0,0.275 ; -0.9,-0.35 0.9,-0.35 0.9,0.35 -0.9,0.35 -0.9,-0.35

## INDC1005X04L_WW [mm]
pads (2):
  rect 0.65x0.5 smd: 1(-0.475,0) 2(0.475,0)
Top Overlay:
  lines w0.152: -0.25,-0.35 -0.9,-0.35 -0.9,0.35 -0.25,0.35 ; 0.25,-0.35 0.9,-0.35 0.9,0.35 0.25,0.35
Mechanical 7:
  lines w0.1: -0.525,-0.275 -0.525,0.275 0.525,0.275 0.525,-0.275 -0.525,-0.275
  text ".Designator" at -0.432,-0.152 h0.3
Mechanical 15:
  lines w0.1: -0.275,0 0.275,0 ; 0,-0.275 0,0.275 ; -0.9,-0.35 -0.9,0.35 0.9,0.35 0.9,-0.35 -0.9,-0.35
3D body "User Library-INDC1005X50-MURATA_LQW15A.STEP": height 0.51, standoff 0, extent -0.5,-0.3 0.5,0.3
